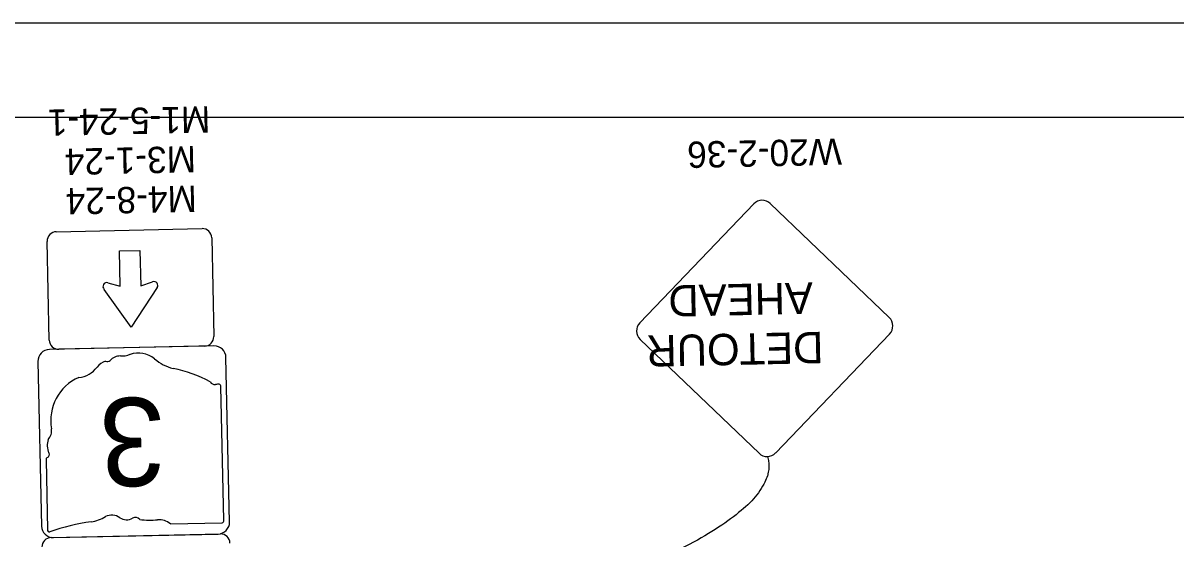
# Model space of a CAD drawing. Extents: x -15.3 to 34, y 0 to 22.
# Drawn here: x 5.53 to 11.66, y 19.26 to 22 of the extents above; entities that cross this region are included whole.
import ezdxf

# ---------------------------------------------------------------- set-up
doc = ezdxf.new("R2010")
doc.units = 0
for name, color, linetype in [('SC_Scratch1', 7, 'Continuous'), ('SH_Border', 7, 'Continuous'), ('SH_Cut_Line', 7, 'Continuous'), ('SH_Text', 7, 'Continuous'), ('SN_P_Signs', 7, 'Continuous')]:
    doc.layers.add(name, color=color, linetype=linetype)

msp = doc.modelspace()

# ---------------------------------------------------------------- linework, layer by layer
at = {"layer": 'SH_Border'}
msp.add_lwpolyline([(1.5, 21.5), (33.5, 21.5), (33.5, 0.5), (1.5, 0.5)], close=True, dxfattribs=at)
at = {"layer": 'SH_Cut_Line'}
msp.add_lwpolyline([(0, 0), (34, 0), (34, 22), (0, 22)], close=True, dxfattribs=at)
at = {"layer": 'SH_Text'}
msp.add_open_spline([(9.492, 19.6955), (9.5648, 19.4628), (8.3529, 18.8728), (8.6057, 18.3944), (8.9661, 17.4512)], degree=2, dxfattribs=at)
at = {"layer": 'SN_P_Signs'}
for p, q in [((5.7117, 20.8905), (6.4865, 20.9071)), ((5.674, 20.3146), (5.6628, 20.8394)), ((6.5376, 20.8582), (6.5488, 20.3333)), ((6.0468, 20.7883), (6.1562, 20.7907)), ((6.0508, 20.6009), (6.0468, 20.7883)), ((6.1562, 20.7907), (6.1602, 20.6032)), ((5.9862, 20.6194), (6.0508, 20.6009)), ((6.2479, 20.5932), (6.1102, 20.3833)), ((6.1602, 20.6032), (6.2238, 20.6245)), ((6.1102, 20.3833), (5.9661, 20.5843)), ((6.4999, 20.2822), (5.7251, 20.2656)), ((6.6017, 19.3563), (6.5865, 20.0676)), ((5.6571, 19.6785), (5.6651, 19.3063)), ((5.6572, 19.6784), (5.6571, 19.6785)), ((6.3182, 19.3379), (6.5927, 19.3438)), ((5.684, 19.2645), (6.5838, 19.2838))]:
    msp.add_line(p, q, dxfattribs=at)
for points in [[(8.8137, 20.4065), (9.419, 21.0383)], [(9.5074, 21.0402), (10.1392, 20.4349)], [(9.4474, 19.7128), (8.8156, 20.3182)], [(10.1411, 20.3465), (9.5358, 19.7147)], [(6.5499, 20.2833), (5.6751, 20.2646)], [(5.6139, 20.2007), (5.6327, 19.3259)], [(6.6324, 19.3473), (6.6137, 20.2221)], [(5.6965, 19.2648), (6.5713, 19.2835)]]:
    msp.add_lwpolyline(points, dxfattribs=at)
for centre, radius, start, end in [((9.4641, 20.9951), 0.0625, 46.22636, 136.22636), ((6.4876, 20.8571), 0.05, 1.22636, 91.22636), ((5.7128, 20.8405), 0.05, 91.22636, 181.22636), ((5.9805, 20.5993), 0.0209, 74.02176, 226.23592), ((6.2304, 20.6047), 0.0209, 326.63758, 108.43097), ((10.096, 20.3898), 0.0625, 316.22636, 46.22636), ((8.8588, 20.3633), 0.0625, 136.22636, 226.22636), ((5.724, 20.3156), 0.05, 181.22636, 271.22636), ((6.4988, 20.3322), 0.05, 271.22636, 1.22636), ((5.6764, 20.2021), 0.0625, 91.22636, 181.22636), ((6.0526, 20.1541), 0.0759, 90.00338, 136.77564), ((6.0588, 20.347), 0.1171, 266.92149, 292.43631), ((6.1464, 20.1028), 0.1425, 51.92674, 107.5182), ((6.5512, 20.2208), 0.0625, 1.22636, 91.22636), ((5.8183, 20.251), 0.1362, 275.62949, 323.80311), ((5.9936, 20.1239), 0.0803, 104.09955, 144.50347), ((5.9824, 20.2215), 0.0214, 246.97809, 313.87479), ((6.3835, 20.383), 0.2246, 228.41052, 257.06234), ((6.1891, 19.4608), 0.7179, 61.63929, 78.42486), ((5.9309, 19.8875), 0.2487, 113.53525, 190.2122), ((6.556, 20.108), 0.0302, 210.97474, 274.49811), ((6.5755, 19.9961), 0.0836, 88.56536, 101.83022), ((6.5756, 20.069), 0.011, 353.18475, 79.53298), ((5.6164, 19.8334), 0.0705, 318.03286, 8.15596), ((5.7607, 19.7551), 0.097, 161.25933, 204.87593), ((5.6682, 19.6801), 0.0112, 110.83017, 188.96049), ((5.6589, 19.7058), 0.0162, 289.17035, 31.56333), ((9.4906, 19.7579), 0.0625, 226.22636, 316.22636), ((5.8671, 19.5457), 0.2, 278.57254, 301.99522), ((6.0065, 19.3077), 0.076, 55.08257, 116.05455), ((6.0856, 19.4223), 0.0632, 235.69305, 300.36749), ((6.132, 19.341), 0.0304, 41.01842, 118.32873), ((5.6952, 19.3273), 0.0625, 181.22636, 271.22636), ((5.6755, 19.305), 0.0104, 173.08845, 278.96436), ((6.0193, 18.3613), 0.9942, 97.07083, 110.13282), ((6.2094, 19.7352), 0.3782, 261.71305, 276.21463), ((6.2546, 19.254), 0.1053, 52.84587, 92.33825), ((6.57, 19.346), 0.0625, 271.22636, 1.22636), ((6.591, 19.3545), 0.0109, 279.35647, 9.35647), ((5.6851, 19.2146), 0.05, 91.22636, 181.22636), ((6.5849, 19.2338), 0.05, 1.22636, 91.22636)]:
    msp.add_arc(centre, radius, start, end, dxfattribs=at)

# ---------------------------------------------------------------- texts
at = {"layer": 'SC_Scratch1'}
for s, p in [('M1-5-24-1', (6.5285, 21.5582)), ('M3-1-24', (6.4525, 21.3466)), ('W20-2-36', (9.8862, 21.3867)), ('M4-8-24', (6.457, 21.1366))]:
    msp.add_text(s, height=0.14, rotation=181.22636, dxfattribs=at).set_placement(p)
at = {"layer": 'SN_P_Signs'}
for s, height, p in [('AHEAD', 0.16667, (9.7321, 20.6216)), ('DETOUR', 0.16667, (9.7877, 20.3589)), ('3', 0.4688, (6.2854, 20.011))]:
    msp.add_text(s, height=height, rotation=181.22636, dxfattribs=at).set_placement(p)

doc.saveas('drawing.dxf')
